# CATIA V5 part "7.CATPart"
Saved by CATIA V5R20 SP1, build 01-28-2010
Part number: 7
Publications: "LD", "D", "L", "Droite.2", "Droite.3", "Droite.4", "Plan.1", "D1", "Droite.5", "Droite.6"
Bounding box of the stored display mesh (mm): x 0 to 0, y 20 to 58.259, z 34.8 to 109.283
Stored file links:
  C:\Users\Geoffray\Documents\Ifma\IAO\Exercice IAO\Catia\7.CATPart
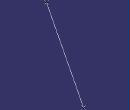
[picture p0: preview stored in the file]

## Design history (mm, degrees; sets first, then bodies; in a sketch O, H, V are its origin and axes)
Parameters
  LD = 100 mm
Body1 (main body)
  Point1 "C": stored without definition
  Point2 "C": stored without definition
  Line1: stored without definition
  Sketch1 on yz-plane, origin (0, 0, 0), H (0, 1, 0), V (0, 0, 1)
    circle A1 centre (76.6113, 26.8506) radius 100
    point P1 (76.6113, 26.8506)
    reference projected point E1 (76.6113, 26.8506) from Point1
    reference projected point E2 (76.6113, 26.8506) from Point2
    line L1 (20, 164.8059) -> (20, 85.4138)
    reference projected line E3 (20, 100) -> (20, 150) from Line1
    point P4 (20, 109.2834)
    point P5 (20, -55.5822)
    distance E2 A1 = 100 {= LD}
    coincidence: P1 E1, L1 E3, A1 P4, L1 P4, A1 P5, L1 P5
    vertical: L1 V
  Point3 "C": stored without definition
  Point4 "L": (0, 0, 0), relative to Sketch1.P4
  Line2: type PtDir, RefPoint Point4, Direction yz-plane, Start -20, End 20
  Plane1: type Offset, RefPlane yz-plane, Offset 0
  Point5 "D": stored without definition
  Point6 "D": (0, 0, 0), relative to Point5
  Line3: type PtDir, RefPoint Point6, Direction yz-plane, Start -20, End 20
  Line4: type PtPt, FirstPoint Point6, SecondPoint Point4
